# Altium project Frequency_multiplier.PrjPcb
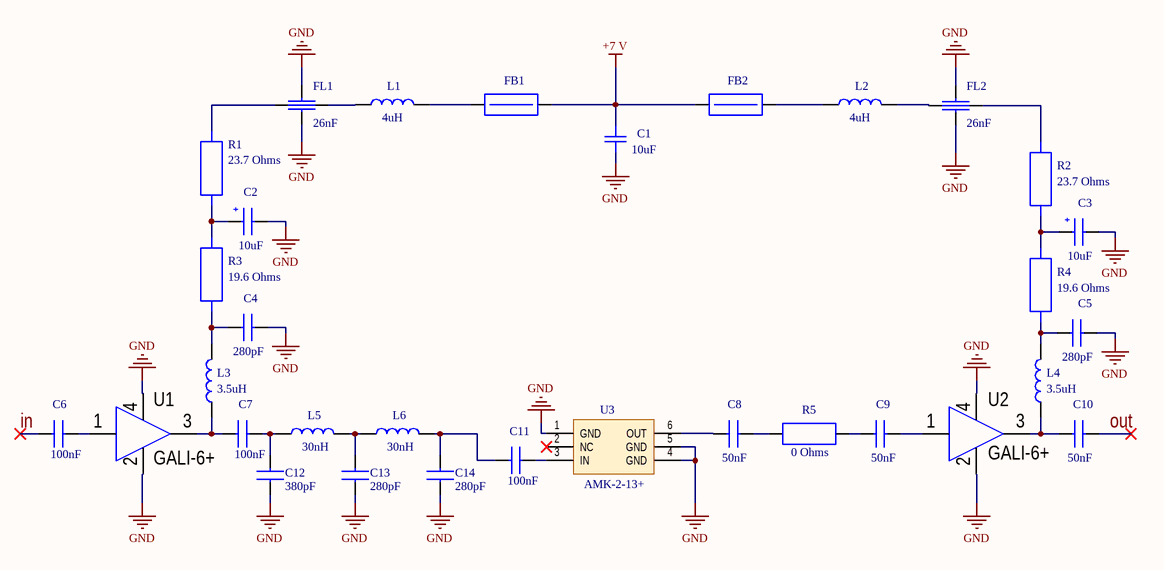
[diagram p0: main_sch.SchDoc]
1 sheet, 32 parts. Net scope: global (net labels, ports and power ports of the same name join across sheets).
Board file: main_pcb.PcbDoc

## Sheet main_sch.SchDoc
size A4; SheetNumber: 1; SheetTotal: 1

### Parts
C1  10uF  [CAPC3216X06N]
C2  10uF  [CAPM7343X15N]
C3  10uF  [CAPM7343X15N]
C4  280pF  [C0603]
C5  280pF  [C0603]
C6  100nF  [C0603]
C7  100nF  [C0603]
C8  50nF  [C0603]
C9  50nF  [C0603]
C10  50nF  [C0603]
C11  100nF  [C0603]
C12  380pF  [C0603]
C13  280pF  [C0603]
C14  280pF  [C0603]
FB1  (no value)  [R0603]
FB2  (no value)  [R0603]
FL1  26nF  [C0805-X2Y]
FL2  26nF  [C0805-X2Y]
L1  4uH  [L1008]
L2  4uH  [L1008]
L3  3.5uH  [L1008]
L4  3.5uH  [L1008]
L5  30nH  [L1008]
L6  30nH  [L1008]
R1  23.7 Ohms  [RESC3216X06N]
R2  23.7 Ohms  [RESC3216X06N]
R3  19.6 Ohms  [RESC3216X06N]
R4  19.6 Ohms  [RESC3216X06N]
R5  0 Ohms  [R0603]
U1  GALI-6+  [DF782]
U2  GALI-6+  [DF782]
U3  AMK-2-13+  [CD542]

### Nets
+7 V: C1.2 FB1.2 FB2.1
GND: C1.1 C2.2 C3.2 C4.2 C5.2 C12.1 C13.1 C14.1 FL1.3 FL1.4 FL2.3 FL2.4 U1.2 U1.4 U2.2 U2.4 U3.1(GND) U3.4(GND) U3.5(GND)
in: C6.1
out: C10.2
NetC2_1: C2.1 R1.1 R3.2
NetC3_1: C3.1 R2.1 R4.2
NetC4_1: C4.1 L3.2 R3.1
NetC5_1: C5.1 L4.2 R4.1
NetC6_2: C6.2 U1.1(in)
NetC7_1: C7.1 L3.1 U1.3(out)
NetC7_2: C7.2 C12.2 L5.1
NetC8_1: C8.1 R5.1
NetC8_2: C8.2 U3.6(OUT)
NetC9_1: C9.1 R5.2
NetC9_2: C9.2 U2.1(in)
NetC10_1: C10.1 L4.1 U2.3(out)
NetC11_1: C11.1 U3.3(IN)
NetC11_2: C11.2 C14.2 L6.2
NetC13_2: C13.2 L5.2 L6.1
NetFB1_1: FB1.1 L1.2
NetFB2_2: FB2.2 L2.1
NetFL1_1: FL1.1 L1.1
NetFL1_2: FL1.2 R1.2
NetFL2_1: FL2.1 R2.2
NetFL2_2: FL2.2 L2.2

Not connected (* = marked no-connect by the designer): U3 2(NC)*

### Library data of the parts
C1 = C1206: smd capacitor, 1206
C2 C3 = C_tantalum_2917: Tantalum capacitor, size 2917
C4-C14 = C0603: CAP CER 0.1UF 50V X7R 0603
FB1 FB2 = FB0603: Ferite beads 0603
FL1 FL2 = C0805-X2Y: CAP 0.1UF 50V X2Y 0805
L1-L6 = 1008CT-: CHIP INDUCTOR SMD 1008
R1-R4 = R1206: smd resistor, 1206
R5 = R0603: RES SMD OHM 1% 0603
U1 U2 = GALI-6+: MMIC 50Ω DC to 4 GHz
U3 = AMK-2-13+: Mini-Circuits Frequency Multiplier X2 50Ω Output 20 to 1000 MHz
